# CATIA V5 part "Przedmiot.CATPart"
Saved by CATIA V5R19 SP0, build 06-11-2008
Part number: Przedmiot
Bounding box of the stored display mesh (mm): x -64.915 to 65, y -64.982 to 64.982, z -48.146 to 21.854
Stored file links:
  D:\POBO\podręcznik\ProcesTechnologiczny\Catia-toczenie\Przedmiot.CATPart
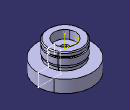
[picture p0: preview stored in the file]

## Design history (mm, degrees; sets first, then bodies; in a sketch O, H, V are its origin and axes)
Body1 "Przedmiot" (main body)
  Sketch1 on zx-plane, origin (0, 0, 0), H (-1, 0, 0), V (0, 0, 1)
    line L1 (-10, -48.1461) -> (-10, 1.8539)
    point P2 (-10, 16.8539)
    line L2 (-26, 21.8539) -> (-39.8787, 21.8539)
    line L3 (-39.8787, 21.8539) -> (-42, 19.7326)
    line L4 (-42, 19.7326) -> (-42, 12.8539)
    line L5 (-42, 12.8539) -> (-39, 12.8539)
    line L6 (-39, 12.8539) -> (-39, 8.8539)
    line L7 (-39, 8.8539) -> (-42, 8.8539)
    point P8 (-42, 8.8539)
    line L8 (-40, -11.641) -> (-40, -18.1461)
    line L9 (-40, -18.1461) -> (-65, -18.1461)
    line L10 (-65, -18.1461) -> (-65, -48.1461)
    line L11 (-65, -48.1461) -> (-10, -48.1461)
    line L12 (-42, 8.8539) -> (-42, -6.1461)
    line L13 (-42, -6.1461) -> (-40, -11.641)
    line L14 (-10, 1.8539) -> (-26, 1.8539)
    line L15 (-26, 1.8539) -> (-26, 21.8539)
    distance V L1 = 10
    distance V L10 = 65
    length L10 = 30
    distance L2 L11 = 70
    vertical: L1 V, L4 V, L6 V, L8 V, L10 V, L12 V, L15 V
    horizontal: L2 H, L5 H, L7 H, L9 H, L11 H, L14 H
    coincidence: P8 L4
  Shaft1: profile Sketch1, axis Sketch1.V, angle 360
  DatumCurve1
